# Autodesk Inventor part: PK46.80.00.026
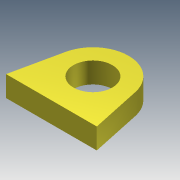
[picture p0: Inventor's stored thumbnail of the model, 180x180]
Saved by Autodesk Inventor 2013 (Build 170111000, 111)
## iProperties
Created: 2005-05
Part Number: PK46.80.00.026
Material: Steel, Mild
Document SubType Name: Modeling
Designer: salex
Manufacturer: Standard
Standards Organization: Custom
Density: 7.86 g/cm^3
Mass: 314.847 g
Surface Area: 100.676 cm^2
Volume: 40.0568 cm^3
Author: salex
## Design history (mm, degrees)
sketch "Эскиз1"
  geometry: L1 (-35, -32)-(35, -32); L2 (35, -32)-(26.887, 5.775); L3 (-35, -32)-(-26.887, 5.775); C1 r 15 at (0, 0); A1 r 27.5 centre (0, 0) between (26.887, 5.775) and (-26.887, 5.775)
  constraints: 6 end point, 2 centre point, 2 point on circle, 2 tangent, 1 coincident, 1 equal length, 1 horizontal, 1 other
  dimensions: "d0" = 32 distance from line of L1 C1.centre; "d1" = 27.5 radius of A1; "d2" = 70 distance of L1.start L1.end; "d3" = 30 diameter of C1
extrude "Выдавливание1" new body sketch "Эскиз1" distance "d4" = 16; taper "d5" = 0 deg
body "Solid1"
